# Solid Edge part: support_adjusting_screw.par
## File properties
Title: Support adjusting screw
Author: Deepak Maini
Template: Normal.par
Last saved by: CADCIM
Revision: 7
Application: Solid Edge
Material: aluminum
Accuracy: 0.99
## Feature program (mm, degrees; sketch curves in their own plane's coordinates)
sketch for "unnamed Protrusion 1" plane through (0, 0, 0) normal (0, -1, 0) x-axis (1, 0, 0)
  circle centre (0, 0) radius 38.1
extrude "unnamed Protrusion 1" add finite 584.2 along +normal
sketch for "ExtrudedCutout_1" plane through (0, -520.7, 0) normal (0, -1, 0) x-axis (1, 0, 0)
extrude "ExtrudedCutout_1" cut finite 76.2 along +normal  Plane_Distance = 63.5 mm
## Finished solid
Body 1: solid body, 5 faces, 4 edges, 0 vertices.
  Faces by surface: plane 3, cylinder 2
  Edges by curve: circle 4
Bounding box of the edges (mm): 76.200 x 584.200 x 76.200, from (-38.1, -584.2, -38.1) to (38.1, 0, 38.1).
Cylindrical faces by radius (mm): R25.4 x1, R38.1 x1
Planar faces by outward normal: +y 1, -y 2
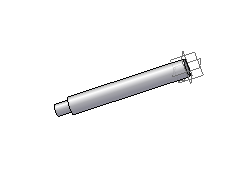
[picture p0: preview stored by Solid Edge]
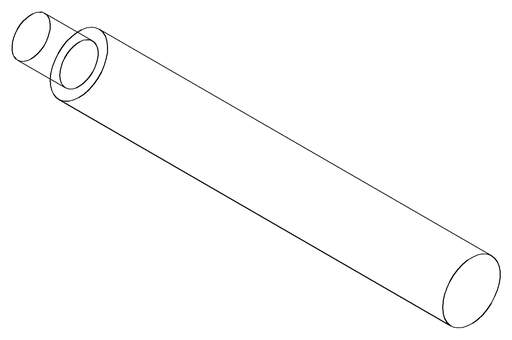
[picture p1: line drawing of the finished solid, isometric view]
